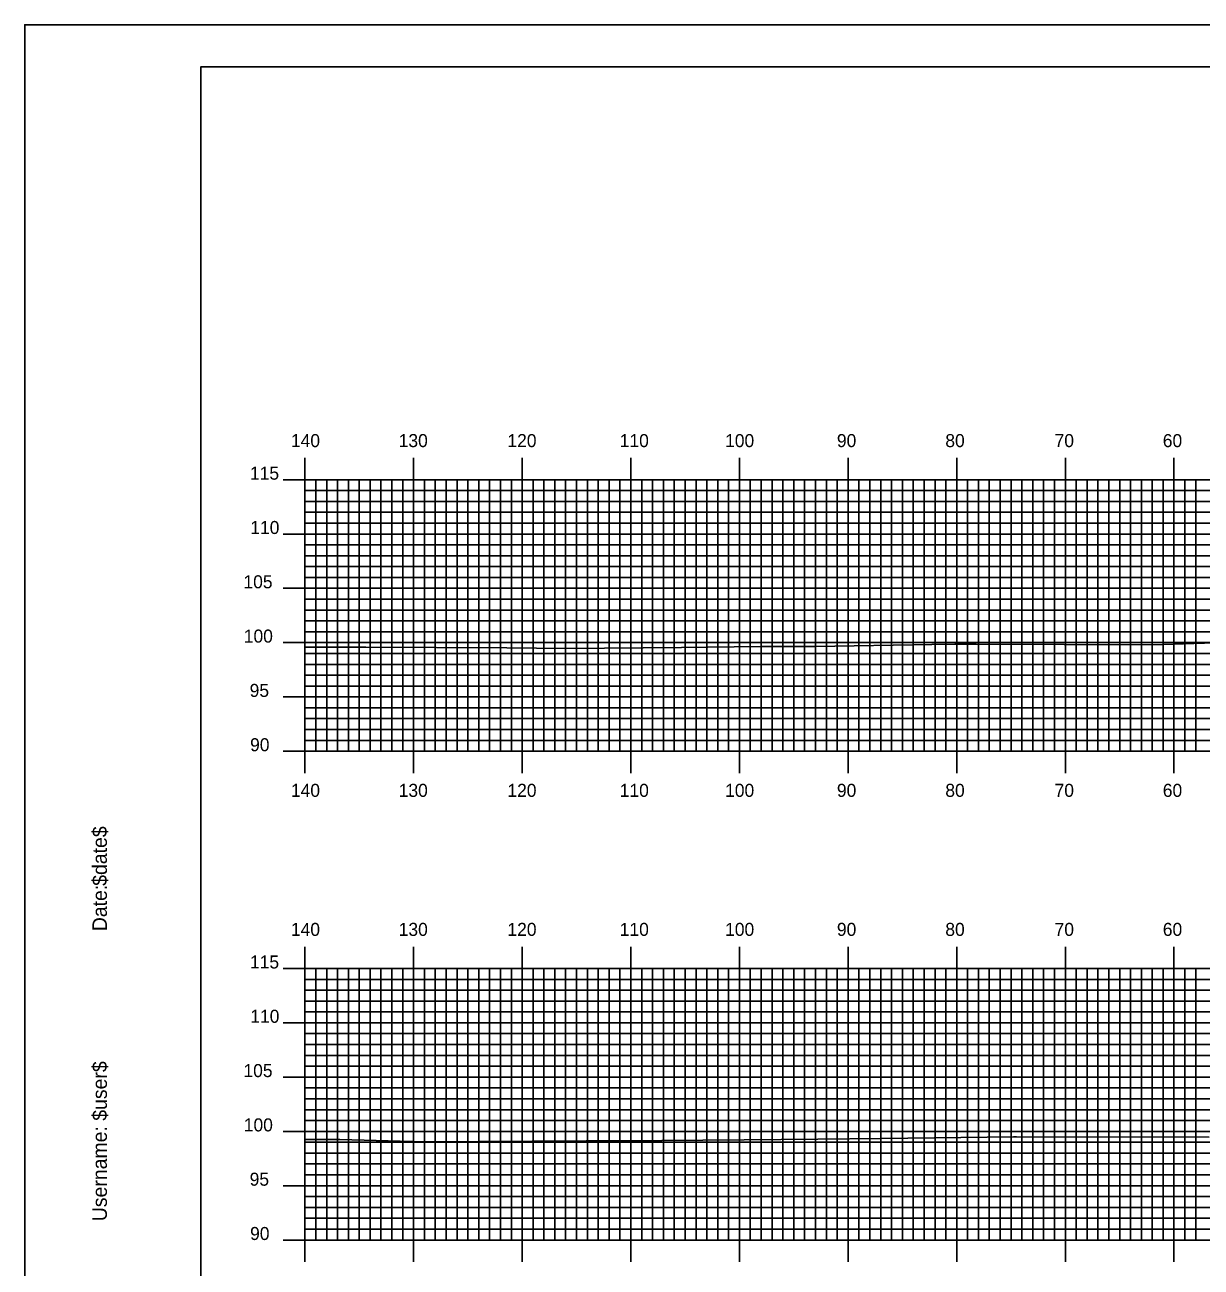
# Model space of a CAD drawing. Extents: x 1765333 to 1765676, y 442591 to 442811.
# Drawn here: x 1765332.6 to 1765440.9, y 442696.2 to 442810.5 of the extents above; entities that cross this region are included whole.
import ezdxf

# ---------------------------------------------------------------- set-up
doc = ezdxf.new("R2010")
doc.units = 0
for name, color, linetype in [('BORDER', 7, 'Continuous'), ('H_V ANNOTATION', 7, 'Continuous'), ('MAJOR', 7, 'Continuous'), ('MINOR', 7, 'Continuous'), ('PLOT BOUNDARY', 7, 'Continuous'), ('S_Roadway_Centerline', 7, 'Continuous')]:
    doc.layers.add(name, color=color, linetype=linetype)

msp = doc.modelspace()

# ---------------------------------------------------------------- linework, layer by layer
at = {"layer": 'BORDER'}
msp.add_lwpolyline([(1765348.77, 442596.67), (1765668.77, 442596.67), (1765668.77, 442806.67), (1765348.77, 442806.67)], close=True, dxfattribs=at)
at = {"layer": 'MAJOR'}
for p, q in [((1765358.37, 442770.67), (1765358.37, 442768.67)), ((1765368.37, 442770.67), (1765368.37, 442768.67)), ((1765378.37, 442770.67), (1765378.37, 442768.67)), ((1765388.37, 442770.67), (1765388.37, 442768.67)), ((1765398.37, 442770.67), (1765398.37, 442768.67)), ((1765408.37, 442770.67), (1765408.37, 442768.67)), ((1765418.37, 442770.67), (1765418.37, 442768.67)), ((1765428.37, 442770.67), (1765428.37, 442768.67)), ((1765438.37, 442770.67), (1765438.37, 442768.67)), ((1765356.37, 442768.67), (1765358.37, 442768.67)), ((1765358.37, 442768.67), (1765638.37, 442768.67)), ((1765358.37, 442743.67), (1765358.37, 442768.67)), ((1765358.37, 442743.67), (1765358.37, 442768.67)), ((1765358.37, 442768.67), (1765638.37, 442768.67)), ((1765368.37, 442743.67), (1765368.37, 442768.67)), ((1765378.37, 442743.67), (1765378.37, 442768.67)), ((1765388.37, 442743.67), (1765388.37, 442768.67)), ((1765398.37, 442743.67), (1765398.37, 442768.67)), ((1765408.37, 442743.67), (1765408.37, 442768.67)), ((1765418.37, 442743.67), (1765418.37, 442768.67)), ((1765428.37, 442743.67), (1765428.37, 442768.67)), ((1765438.37, 442743.67), (1765438.37, 442768.67)), ((1765356.37, 442763.67), (1765358.37, 442763.67)), ((1765358.37, 442763.67), (1765638.37, 442763.67)), ((1765356.37, 442758.67), (1765358.37, 442758.67)), ((1765358.37, 442758.67), (1765638.37, 442758.67)), ((1765356.37, 442753.67), (1765358.37, 442753.67)), ((1765358.37, 442753.67), (1765638.37, 442753.67)), ((1765356.37, 442748.67), (1765358.37, 442748.67)), ((1765358.37, 442748.67), (1765638.37, 442748.67)), ((1765356.37, 442743.67), (1765358.37, 442743.67)), ((1765358.37, 442743.67), (1765638.37, 442743.67)), ((1765358.37, 442743.67), (1765638.37, 442743.67)), ((1765358.37, 442741.66), (1765358.37, 442743.67)), ((1765368.37, 442741.66), (1765368.37, 442743.67)), ((1765378.37, 442741.66), (1765378.37, 442743.67)), ((1765388.37, 442741.66), (1765388.37, 442743.67)), ((1765398.37, 442741.66), (1765398.37, 442743.67)), ((1765408.37, 442741.66), (1765408.37, 442743.67)), ((1765418.37, 442741.66), (1765418.37, 442743.67)), ((1765428.37, 442741.66), (1765428.37, 442743.67)), ((1765438.37, 442741.66), (1765438.37, 442743.67)), ((1765358.37, 442725.67), (1765358.37, 442723.67)), ((1765368.37, 442725.67), (1765368.37, 442723.67)), ((1765378.37, 442725.67), (1765378.37, 442723.67)), ((1765388.37, 442725.67), (1765388.37, 442723.67)), ((1765398.37, 442725.67), (1765398.37, 442723.67)), ((1765408.37, 442725.67), (1765408.37, 442723.67)), ((1765418.37, 442725.67), (1765418.37, 442723.67)), ((1765428.37, 442725.67), (1765428.37, 442723.67)), ((1765438.37, 442725.67), (1765438.37, 442723.67)), ((1765356.37, 442723.67), (1765358.37, 442723.67)), ((1765358.37, 442723.67), (1765638.37, 442723.67)), ((1765358.37, 442698.67), (1765358.37, 442723.67)), ((1765358.37, 442698.67), (1765358.37, 442723.67)), ((1765358.37, 442723.67), (1765638.37, 442723.67)), ((1765368.37, 442698.67), (1765368.37, 442723.67)), ((1765378.37, 442698.67), (1765378.37, 442723.67)), ((1765388.37, 442698.67), (1765388.37, 442723.67)), ((1765398.37, 442698.67), (1765398.37, 442723.67)), ((1765408.37, 442698.67), (1765408.37, 442723.67)), ((1765418.37, 442698.67), (1765418.37, 442723.67)), ((1765428.37, 442698.67), (1765428.37, 442723.67)), ((1765438.37, 442698.67), (1765438.37, 442723.67)), ((1765356.37, 442718.67), (1765358.37, 442718.67)), ((1765358.37, 442718.67), (1765638.37, 442718.67)), ((1765356.37, 442713.67), (1765358.37, 442713.67)), ((1765358.37, 442713.67), (1765638.37, 442713.67)), ((1765356.37, 442708.67), (1765358.37, 442708.67)), ((1765358.37, 442708.67), (1765638.37, 442708.67)), ((1765356.37, 442703.67), (1765358.37, 442703.67)), ((1765358.37, 442703.67), (1765638.37, 442703.67)), ((1765356.37, 442698.67), (1765358.37, 442698.67)), ((1765358.37, 442698.67), (1765638.37, 442698.67)), ((1765358.37, 442698.67), (1765638.37, 442698.67)), ((1765358.37, 442696.66), (1765358.37, 442698.67)), ((1765368.37, 442696.66), (1765368.37, 442698.67)), ((1765378.37, 442696.66), (1765378.37, 442698.67)), ((1765388.37, 442696.66), (1765388.37, 442698.67)), ((1765398.37, 442696.66), (1765398.37, 442698.67)), ((1765408.37, 442696.66), (1765408.37, 442698.67)), ((1765418.37, 442696.66), (1765418.37, 442698.67)), ((1765428.37, 442696.66), (1765428.37, 442698.67)), ((1765438.37, 442696.66), (1765438.37, 442698.67))]:
    msp.add_line(p, q, dxfattribs=at)
at = {"layer": 'MINOR'}
for p, q in [((1765358.37, 442767.67), (1765638.37, 442767.67)), ((1765358.37, 442767.67), (1765360.37, 442767.67)), ((1765359.37, 442743.67), (1765359.37, 442768.67)), ((1765360.37, 442743.67), (1765360.37, 442768.67)), ((1765361.37, 442743.67), (1765361.37, 442768.67)), ((1765362.37, 442743.67), (1765362.37, 442768.67)), ((1765363.37, 442743.67), (1765363.37, 442768.67)), ((1765364.37, 442743.67), (1765364.37, 442768.67)), ((1765365.37, 442743.67), (1765365.37, 442768.67)), ((1765366.37, 442743.67), (1765366.37, 442768.67)), ((1765367.37, 442743.67), (1765367.37, 442768.67)), ((1765369.37, 442743.67), (1765369.37, 442768.67)), ((1765370.37, 442743.67), (1765370.37, 442768.67)), ((1765371.37, 442743.67), (1765371.37, 442768.67)), ((1765372.37, 442743.67), (1765372.37, 442768.67)), ((1765373.37, 442743.67), (1765373.37, 442768.67)), ((1765374.37, 442743.67), (1765374.37, 442768.67)), ((1765375.37, 442743.67), (1765375.37, 442768.67)), ((1765376.37, 442743.67), (1765376.37, 442768.67)), ((1765377.37, 442743.67), (1765377.37, 442768.67)), ((1765379.37, 442743.67), (1765379.37, 442768.67)), ((1765380.37, 442743.67), (1765380.37, 442768.67)), ((1765381.37, 442743.67), (1765381.37, 442768.67)), ((1765382.37, 442743.67), (1765382.37, 442768.67)), ((1765383.37, 442743.67), (1765383.37, 442768.67)), ((1765384.37, 442743.67), (1765384.37, 442768.67)), ((1765385.37, 442743.67), (1765385.37, 442768.67)), ((1765386.37, 442743.67), (1765386.37, 442768.67)), ((1765387.37, 442743.67), (1765387.37, 442768.67)), ((1765389.37, 442743.67), (1765389.37, 442768.67)), ((1765390.37, 442743.67), (1765390.37, 442768.67)), ((1765391.37, 442743.67), (1765391.37, 442768.67)), ((1765392.37, 442743.67), (1765392.37, 442768.67)), ((1765393.37, 442743.67), (1765393.37, 442768.67)), ((1765394.37, 442743.67), (1765394.37, 442768.67)), ((1765395.37, 442743.67), (1765395.37, 442768.67)), ((1765396.37, 442743.67), (1765396.37, 442768.67)), ((1765397.37, 442743.67), (1765397.37, 442768.67)), ((1765399.37, 442743.67), (1765399.37, 442768.67)), ((1765400.37, 442743.67), (1765400.37, 442768.67)), ((1765401.37, 442743.67), (1765401.37, 442768.67)), ((1765402.37, 442743.67), (1765402.37, 442768.67)), ((1765403.37, 442743.67), (1765403.37, 442768.67)), ((1765404.37, 442743.67), (1765404.37, 442768.67)), ((1765405.37, 442743.67), (1765405.37, 442768.67)), ((1765406.37, 442743.67), (1765406.37, 442768.67)), ((1765407.37, 442743.67), (1765407.37, 442768.67)), ((1765409.37, 442743.67), (1765409.37, 442768.67)), ((1765410.37, 442743.67), (1765410.37, 442768.67)), ((1765411.37, 442743.67), (1765411.37, 442768.67)), ((1765412.37, 442743.67), (1765412.37, 442768.67)), ((1765413.37, 442743.67), (1765413.37, 442768.67)), ((1765414.37, 442743.67), (1765414.37, 442768.67)), ((1765415.37, 442743.67), (1765415.37, 442768.67)), ((1765416.37, 442743.67), (1765416.37, 442768.67)), ((1765417.37, 442743.67), (1765417.37, 442768.67)), ((1765419.37, 442743.67), (1765419.37, 442768.67)), ((1765420.37, 442743.67), (1765420.37, 442768.67)), ((1765421.37, 442743.67), (1765421.37, 442768.67)), ((1765422.37, 442743.67), (1765422.37, 442768.67)), ((1765423.37, 442743.67), (1765423.37, 442768.67)), ((1765424.37, 442743.67), (1765424.37, 442768.67)), ((1765425.37, 442743.67), (1765425.37, 442768.67)), ((1765426.37, 442743.67), (1765426.37, 442768.67)), ((1765427.37, 442743.67), (1765427.37, 442768.67)), ((1765429.37, 442743.67), (1765429.37, 442768.67)), ((1765430.37, 442743.67), (1765430.37, 442768.67)), ((1765431.37, 442743.67), (1765431.37, 442768.67)), ((1765432.37, 442743.67), (1765432.37, 442768.67)), ((1765433.37, 442743.67), (1765433.37, 442768.67)), ((1765434.37, 442743.67), (1765434.37, 442768.67)), ((1765435.37, 442743.67), (1765435.37, 442768.67)), ((1765436.37, 442743.67), (1765436.37, 442768.67)), ((1765437.37, 442743.67), (1765437.37, 442768.67)), ((1765439.37, 442743.67), (1765439.37, 442768.67)), ((1765440.37, 442743.67), (1765440.37, 442768.67)), ((1765358.37, 442766.67), (1765638.37, 442766.67)), ((1765358.37, 442766.67), (1765360.37, 442766.67)), ((1765358.37, 442765.67), (1765638.37, 442765.67)), ((1765358.37, 442765.67), (1765360.37, 442765.67)), ((1765358.37, 442764.67), (1765638.37, 442764.67)), ((1765358.37, 442764.67), (1765360.37, 442764.67)), ((1765358.37, 442762.67), (1765638.37, 442762.67)), ((1765358.37, 442762.67), (1765360.37, 442762.67)), ((1765358.37, 442761.67), (1765638.37, 442761.67)), ((1765358.37, 442761.67), (1765360.37, 442761.67)), ((1765358.37, 442760.67), (1765638.37, 442760.67)), ((1765358.37, 442760.67), (1765360.37, 442760.67)), ((1765358.37, 442759.67), (1765638.37, 442759.67)), ((1765358.37, 442759.67), (1765360.37, 442759.67)), ((1765358.37, 442757.67), (1765638.37, 442757.67)), ((1765358.37, 442757.67), (1765360.37, 442757.67)), ((1765358.37, 442756.67), (1765638.37, 442756.67)), ((1765358.37, 442756.67), (1765360.37, 442756.67)), ((1765358.37, 442755.67), (1765638.37, 442755.67)), ((1765358.37, 442755.67), (1765360.37, 442755.67)), ((1765358.37, 442754.67), (1765638.37, 442754.67)), ((1765358.37, 442754.67), (1765360.37, 442754.67)), ((1765358.37, 442752.67), (1765638.37, 442752.67)), ((1765358.37, 442752.67), (1765360.37, 442752.67)), ((1765358.37, 442751.67), (1765638.37, 442751.67)), ((1765358.37, 442751.67), (1765360.37, 442751.67)), ((1765358.37, 442750.67), (1765638.37, 442750.67)), ((1765358.37, 442750.67), (1765360.37, 442750.67)), ((1765358.37, 442749.67), (1765638.37, 442749.67)), ((1765358.37, 442749.67), (1765360.37, 442749.67)), ((1765358.37, 442747.67), (1765638.37, 442747.67)), ((1765358.37, 442747.67), (1765360.37, 442747.67)), ((1765358.37, 442746.67), (1765638.37, 442746.67)), ((1765358.37, 442746.67), (1765360.37, 442746.67)), ((1765358.37, 442745.67), (1765638.37, 442745.67)), ((1765358.37, 442745.67), (1765360.37, 442745.67)), ((1765358.37, 442744.67), (1765638.37, 442744.67)), ((1765358.37, 442744.67), (1765360.37, 442744.67)), ((1765359.37, 442698.67), (1765359.37, 442723.67)), ((1765360.37, 442698.67), (1765360.37, 442723.67)), ((1765361.37, 442698.67), (1765361.37, 442723.67)), ((1765362.37, 442698.67), (1765362.37, 442723.67)), ((1765363.37, 442698.67), (1765363.37, 442723.67)), ((1765364.37, 442698.67), (1765364.37, 442723.67)), ((1765365.37, 442698.67), (1765365.37, 442723.67)), ((1765366.37, 442698.67), (1765366.37, 442723.67)), ((1765367.37, 442698.67), (1765367.37, 442723.67)), ((1765369.37, 442698.67), (1765369.37, 442723.67)), ((1765370.37, 442698.67), (1765370.37, 442723.67)), ((1765371.37, 442698.67), (1765371.37, 442723.67)), ((1765372.37, 442698.67), (1765372.37, 442723.67)), ((1765373.37, 442698.67), (1765373.37, 442723.67)), ((1765374.37, 442698.67), (1765374.37, 442723.67)), ((1765375.37, 442698.67), (1765375.37, 442723.67)), ((1765376.37, 442698.67), (1765376.37, 442723.67)), ((1765377.37, 442698.67), (1765377.37, 442723.67)), ((1765379.37, 442698.67), (1765379.37, 442723.67)), ((1765380.37, 442698.67), (1765380.37, 442723.67)), ((1765381.37, 442698.67), (1765381.37, 442723.67)), ((1765382.37, 442698.67), (1765382.37, 442723.67)), ((1765383.37, 442698.67), (1765383.37, 442723.67)), ((1765384.37, 442698.67), (1765384.37, 442723.67)), ((1765385.37, 442698.67), (1765385.37, 442723.67)), ((1765386.37, 442698.67), (1765386.37, 442723.67)), ((1765387.37, 442698.67), (1765387.37, 442723.67)), ((1765389.37, 442698.67), (1765389.37, 442723.67)), ((1765390.37, 442698.67), (1765390.37, 442723.67)), ((1765391.37, 442698.67), (1765391.37, 442723.67)), ((1765392.37, 442698.67), (1765392.37, 442723.67)), ((1765393.37, 442698.67), (1765393.37, 442723.67)), ((1765394.37, 442698.67), (1765394.37, 442723.67)), ((1765395.37, 442698.67), (1765395.37, 442723.67)), ((1765396.37, 442698.67), (1765396.37, 442723.67)), ((1765397.37, 442698.67), (1765397.37, 442723.67)), ((1765399.37, 442698.67), (1765399.37, 442723.67)), ((1765400.37, 442698.67), (1765400.37, 442723.67)), ((1765401.37, 442698.67), (1765401.37, 442723.67)), ((1765402.37, 442698.67), (1765402.37, 442723.67)), ((1765403.37, 442698.67), (1765403.37, 442723.67)), ((1765404.37, 442698.67), (1765404.37, 442723.67)), ((1765405.37, 442698.67), (1765405.37, 442723.67)), ((1765406.37, 442698.67), (1765406.37, 442723.67)), ((1765407.37, 442698.67), (1765407.37, 442723.67)), ((1765409.37, 442698.67), (1765409.37, 442723.67)), ((1765410.37, 442698.67), (1765410.37, 442723.67)), ((1765411.37, 442698.67), (1765411.37, 442723.67)), ((1765412.37, 442698.67), (1765412.37, 442723.67)), ((1765413.37, 442698.67), (1765413.37, 442723.67)), ((1765414.37, 442698.67), (1765414.37, 442723.67)), ((1765415.37, 442698.67), (1765415.37, 442723.67)), ((1765416.37, 442698.67), (1765416.37, 442723.67)), ((1765417.37, 442698.67), (1765417.37, 442723.67)), ((1765419.37, 442698.67), (1765419.37, 442723.67)), ((1765420.37, 442698.67), (1765420.37, 442723.67)), ((1765421.37, 442698.67), (1765421.37, 442723.67)), ((1765422.37, 442698.67), (1765422.37, 442723.67)), ((1765423.37, 442698.67), (1765423.37, 442723.67)), ((1765424.37, 442698.67), (1765424.37, 442723.67)), ((1765425.37, 442698.67), (1765425.37, 442723.67)), ((1765426.37, 442698.67), (1765426.37, 442723.67)), ((1765427.37, 442698.67), (1765427.37, 442723.67)), ((1765429.37, 442698.67), (1765429.37, 442723.67)), ((1765430.37, 442698.67), (1765430.37, 442723.67)), ((1765431.37, 442698.67), (1765431.37, 442723.67)), ((1765432.37, 442698.67), (1765432.37, 442723.67)), ((1765433.37, 442698.67), (1765433.37, 442723.67)), ((1765434.37, 442698.67), (1765434.37, 442723.67)), ((1765435.37, 442698.67), (1765435.37, 442723.67)), ((1765436.37, 442698.67), (1765436.37, 442723.67)), ((1765437.37, 442698.67), (1765437.37, 442723.67)), ((1765439.37, 442698.67), (1765439.37, 442723.67)), ((1765440.37, 442698.67), (1765440.37, 442723.67)), ((1765358.37, 442722.67), (1765638.37, 442722.67)), ((1765358.37, 442722.67), (1765360.37, 442722.67)), ((1765358.37, 442721.67), (1765638.37, 442721.67)), ((1765358.37, 442721.67), (1765360.37, 442721.67)), ((1765358.37, 442720.67), (1765638.37, 442720.67)), ((1765358.37, 442720.67), (1765360.37, 442720.67)), ((1765358.37, 442719.67), (1765638.37, 442719.67)), ((1765358.37, 442719.67), (1765360.37, 442719.67)), ((1765358.37, 442717.67), (1765638.37, 442717.67)), ((1765358.37, 442717.67), (1765360.37, 442717.67)), ((1765358.37, 442716.67), (1765638.37, 442716.67)), ((1765358.37, 442716.67), (1765360.37, 442716.67)), ((1765358.37, 442715.67), (1765638.37, 442715.67)), ((1765358.37, 442715.67), (1765360.37, 442715.67)), ((1765358.37, 442714.67), (1765638.37, 442714.67)), ((1765358.37, 442714.67), (1765360.37, 442714.67)), ((1765358.37, 442712.67), (1765638.37, 442712.67)), ((1765358.37, 442712.67), (1765360.37, 442712.67)), ((1765358.37, 442711.67), (1765638.37, 442711.67)), ((1765358.37, 442711.67), (1765360.37, 442711.67)), ((1765358.37, 442710.67), (1765638.37, 442710.67)), ((1765358.37, 442710.67), (1765360.37, 442710.67)), ((1765358.37, 442709.67), (1765638.37, 442709.67)), ((1765358.37, 442709.67), (1765360.37, 442709.67)), ((1765358.37, 442707.67), (1765638.37, 442707.67)), ((1765358.37, 442707.67), (1765360.37, 442707.67)), ((1765358.37, 442706.67), (1765638.37, 442706.67)), ((1765358.37, 442706.67), (1765360.37, 442706.67)), ((1765358.37, 442705.67), (1765638.37, 442705.67)), ((1765358.37, 442705.67), (1765360.37, 442705.67)), ((1765358.37, 442704.67), (1765638.37, 442704.67)), ((1765358.37, 442704.67), (1765360.37, 442704.67)), ((1765358.37, 442702.67), (1765638.37, 442702.67)), ((1765358.37, 442702.67), (1765360.37, 442702.67)), ((1765358.37, 442701.67), (1765638.37, 442701.67)), ((1765358.37, 442701.67), (1765360.37, 442701.67)), ((1765358.37, 442700.67), (1765638.37, 442700.67)), ((1765358.37, 442700.67), (1765360.37, 442700.67)), ((1765358.37, 442699.67), (1765638.37, 442699.67)), ((1765358.37, 442699.67), (1765360.37, 442699.67))]:
    msp.add_line(p, q, dxfattribs=at)
at = {"layer": 'PLOT BOUNDARY'}
msp.add_lwpolyline([(1765332.58, 442590.55), (1765672.58, 442590.55), (1765672.58, 442810.55), (1765332.58, 442810.55)], close=True, dxfattribs=at)
at = {"layer": 'S_Roadway_Centerline'}
for points in [[(1765358.37, 442753.24), (1765363.96, 442753.26), (1765376.95, 442753.19), (1765382.43, 442753.14), (1765393.04, 442753.21), (1765400.32, 442753.3), (1765405.37, 442753.3), (1765416.09, 442753.5), (1765418.21, 442753.52), (1765420.16, 442753.53), (1765436.37, 442753.47), (1765442.13, 442753.64)], [(1765358.37, 442707.92), (1765361.59, 442707.92), (1765369.38, 442707.7), (1765384.26, 442707.79), (1765386.4, 442707.81), (1765387.41, 442707.8), (1765398.81, 442707.89), (1765405.59, 442707.97), (1765411.45, 442708.03), (1765423.61, 442708.16), (1765423.69, 442708.16), (1765423.88, 442708.16), (1765441.62, 442708.15)]]:
    msp.add_lwpolyline(points, dxfattribs=at)

# ---------------------------------------------------------------- texts
at = {"layer": 'BORDER'}
for s, p in [('$date$', (1765340.14, 442731.28)), ('Date:', (1765340.14, 442727.1)), ('$user$', (1765340.14, 442709.65)), ('Username:', (1765340.14, 442700.4))]:
    msp.add_text(s, height=1.339, rotation=90, dxfattribs=at).set_placement(p)
at = {"layer": 'H_V ANNOTATION'}
for s, p in [('140', (1765357.08, 442771.67)), ('130', (1765367, 442771.67)), ('120', (1765377.01, 442771.67)), ('110', (1765387.35, 442771.67)), ('100', (1765397.05, 442771.67)), ('90', (1765407.34, 442771.67)), ('80', (1765417.32, 442771.67)), ('70', (1765427.38, 442771.67)), ('60', (1765437.34, 442771.67)), ('115', (1765353.31, 442768.67)), ('110', (1765353.34, 442763.67)), ('105', (1765352.71, 442758.67)), ('100', (1765352.74, 442753.67)), ('95', (1765353.28, 442748.67)), ('90', (1765353.32, 442743.67)), ('140', (1765357.08, 442739.47)), ('130', (1765367, 442739.47)), ('120', (1765377.01, 442739.47)), ('110', (1765387.35, 442739.47)), ('100', (1765397.05, 442739.47)), ('90', (1765407.34, 442739.47)), ('80', (1765417.32, 442739.47)), ('70', (1765427.38, 442739.47)), ('60', (1765437.34, 442739.47)), ('140', (1765357.08, 442726.67)), ('130', (1765367, 442726.67)), ('120', (1765377.01, 442726.67)), ('110', (1765387.35, 442726.67)), ('100', (1765397.05, 442726.67)), ('90', (1765407.34, 442726.67)), ('80', (1765417.32, 442726.67)), ('70', (1765427.38, 442726.67)), ('60', (1765437.34, 442726.67)), ('115', (1765353.31, 442723.67)), ('110', (1765353.34, 442718.67)), ('105', (1765352.71, 442713.67)), ('100', (1765352.74, 442708.67)), ('95', (1765353.28, 442703.67)), ('90', (1765353.32, 442698.67))]:
    msp.add_text(s, height=1.2, dxfattribs=at).set_placement(p)
at = {"layer": 'MAJOR'}
for p in [(1765358.36, 442743.67), (1765358.36, 442698.67)]:
    msp.add_text('-', height=0.012, dxfattribs=at).set_placement(p)

doc.saveas('drawing.dxf')
